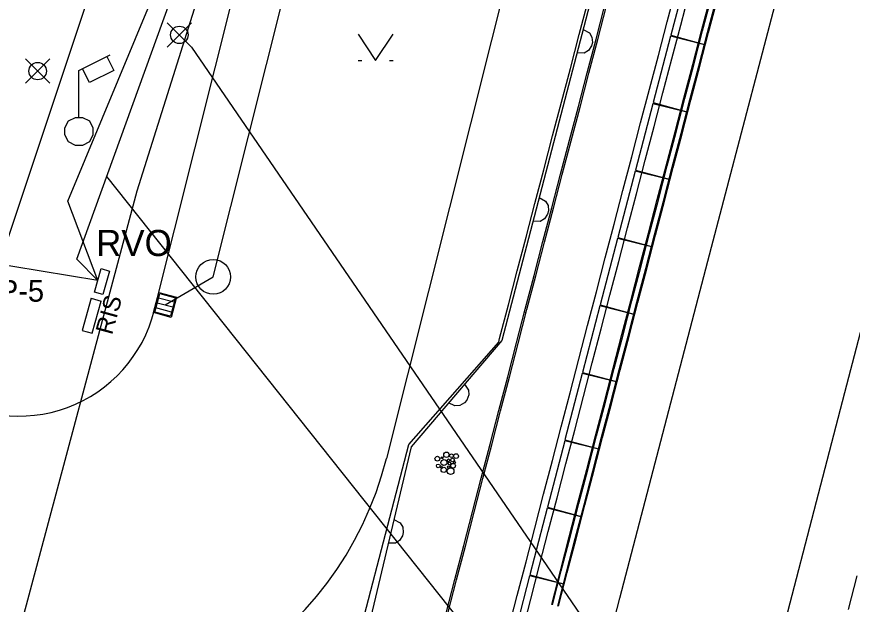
# Model space of a CAD drawing. Extents: x -733601 to -733291, y -1137892 to -1137187.
# Drawn here: x -733460.25 to -733436.26, y -1137631.66 to -1137614.8 of the extents above; entities that cross this region are included whole.
import ezdxf

# ---------------------------------------------------------------- set-up
doc = ezdxf.new("R2010")
doc.units = 0
for name, color, linetype in [('Default', 7, 'Continuous'), ('SIT_PROJ', 7, 'Continuous'), ('SIT_PUV_BUS', 7, 'Continuous'), ('SIT_PUV_ZELEZNICE', 7, 'Continuous')]:
    doc.layers.add(name, color=color, linetype=linetype)

# ---------------------------------------------------------------- blocks, each defined once
blk = doc.blocks.new('DOPRAVA_4$0$SYMB1230')
at = {"layer": 'Default'}
for p, q in [((-0.1, -0.329897), (-0.1, -0.020619)), ((0, -0.020619), (0, -0.329897)), ((0.1, -0.020619), (0.1, -0.329897)), ((-0.1, -0.325773), (-0.1, -0.329897))]:
    blk.add_line(p, q, dxfattribs=at)
for points in [[(-0.2, 0), (0.2, 0), (0.2, -0.35), (-0.2, -0.35)], [(-0.182831, -0.020619), (0.181696, -0.020619), (0.181696, -0.329897), (-0.182831, -0.329897)]]:
    blk.add_lwpolyline(points, close=True, dxfattribs=at)
blk = doc.blocks.new('POINT_DISPLAY')
at = {"layer": 'Default'}
for p, q in [((-0.7, -0.7), (0.7, 0.7)), ((-0.7, 0.7), (0.7, -0.7))]:
    blk.add_line(p, q, dxfattribs=at)
blk.add_circle((0, 0), 0.5, dxfattribs=at)
blk = doc.blocks.new('vytyc_bod_MP')
at = {"layer": 'Default'}
blk.add_blockref('POINT_DISPLAY', (0, 0), dxfattribs=at)

msp = doc.modelspace()

# ---------------------------------------------------------------- linework, layer by layer
at = {"layer": 'SIT_PROJ'}
for points in [[(-733457.917, -1137622.364), (-733458.777, -1137620.095), (-733456.339, -1137614.218), (-733457.273, -1137613.333), (-733455.913, -1137612.939), (-733454.69, -1137608.9), (-733452.562, -1137600.661), (-733449.967, -1137590.732), (-733451.007, -1137589.721), (-733449.679, -1137589.475), (-733444.067, -1137566.075), (-733444.902, -1137565.405), (-733443.754, -1137565.269), (-733437.875, -1137541.673), (-733438.793, -1137541.042), (-733437.71, -1137541.027), (-733436.525, -1137536.63), (-733452.133, -1137532.662), (-733452.807, -1137531.541)], [(-733456.299, -1137623.235), (-733433.573, -1137532.72)], [(-733429.102, -1137545.713), (-733449.631, -1137627.477)], [(-733457.917, -1137622.364), (-733458.523, -1137621.757), (-733455.851, -1137614.377), (-733455.422, -1137613.019), (-733451.725, -1137599.481), (-733449.522, -1137590.912), (-733449.164, -1137589.482), (-733443.392, -1137565.741), (-733438.875, -1137547.904)], [(-733457.917, -1137622.364), (-733464.433, -1137621.3), (-733463.63, -1137616.478), (-733471.299, -1137614.635), (-733471.621, -1137613.836), (-733472.5, -1137612.391), (-733468.724, -1137597.945), (-733462.8, -1137574.579)], [(-733454.604, -1137622.264), (-733444.427, -1137581.731)], [(-733455.227, -1137615.669), (-733439.093, -1137639.217), (-733439.093, -1137639.217)], [(-733457.665, -1137619.387), (-733442.89, -1137637.96), (-733442.89, -1137637.96)], [(-733455.98, -1137623.071), (-733454.604, -1137622.264)]]:
    msp.add_lwpolyline(points, dxfattribs=at)
msp.add_lwpolyline([(-733457.584, -1137622.097), (-733457.771, -1137622.772), (-733458.011, -1137622.701), (-733457.824, -1137622.027)], close=True, dxfattribs=at)
msp.add_lwpolyline([(-733457.584, -1137622.097), (-733457.771, -1137622.772), (-733458.011, -1137622.701), (-733457.824, -1137622.027)], close=True, dxfattribs=at)
msp.add_circle((-733454.604, -1137622.265), 0.5, dxfattribs=at)
for centre, radius, start in [((-733460.178, -1137622.261), 4, 234.8056), ((-733459.33, -1137625.042), 10, 255.9059)]:
    msp.add_arc(centre, radius, start, 345.9059, dxfattribs=at)
at = {"layer": 'SIT_PUV_BUS'}
for p, q in [((-733440.9, -1137603.4), (-733446.32, -1137624.09)), ((-733457.34, -1137611.69), (-733463.99, -1137631.53)), ((-733454.61, -1137612.85), (-733456.8, -1137619.8)), ((-733443.981, -1137615.161), (-733443.8, -1137615.261)), ((-733450.44, -1137615.3), (-733449.94, -1137616.05)), ((-733449.94, -1137616.05), (-733449.44, -1137615.3)), ((-733443.8, -1137615.261), (-733443.729, -1137615.383)), ((-733443.729, -1137615.383), (-733443.719, -1137615.54)), ((-733443.744, -1137615.637), (-733443.831, -1137615.77)), ((-733443.719, -1137615.54), (-733443.744, -1137615.637)), ((-733458.46, -1137616.34), (-733457.56, -1137615.89)), ((-733443.953, -1137615.841), (-733444.159, -1137615.839)), ((-733443.831, -1137615.77), (-733443.953, -1137615.841)), ((-733457.66, -1137615.94), (-733457.46, -1137616.34)), ((-733450.44, -1137616.05), (-733450.34, -1137616.05)), ((-733449.54, -1137616.05), (-733449.44, -1137616.05)), ((-733458.46, -1137617.69), (-733458.46, -1137616.34)), ((-733458.16, -1137616.69), (-733458.36, -1137616.29)), ((-733457.46, -1137616.34), (-733458.16, -1137616.69)), ((-733458.86, -1137617.99), (-733458.76, -1137617.79)), ((-733458.76, -1137617.79), (-733458.56, -1137617.69)), ((-733458.56, -1137617.69), (-733458.36, -1137617.69)), ((-733458.36, -1137617.69), (-733458.16, -1137617.79)), ((-733458.16, -1137617.79), (-733458.06, -1137617.99)), ((-733458.86, -1137618.19), (-733458.86, -1137617.99)), ((-733458.06, -1137617.99), (-733458.06, -1137618.19)), ((-733458.76, -1137618.39), (-733458.86, -1137618.19)), ((-733458.06, -1137618.19), (-733458.16, -1137618.39)), ((-733458.56, -1137618.49), (-733458.76, -1137618.39)), ((-733458.36, -1137618.49), (-733458.56, -1137618.49)), ((-733458.16, -1137618.39), (-733458.36, -1137618.49)), ((-733456.8, -1137619.8), (-733461.75, -1137638.34)), ((-733445.241, -1137619.991), (-733445.06, -1137620.091)), ((-733445.06, -1137620.091), (-733444.989, -1137620.213)), ((-733444.989, -1137620.213), (-733444.979, -1137620.37)), ((-733445.004, -1137620.467), (-733445.091, -1137620.6)), ((-733444.979, -1137620.37), (-733445.004, -1137620.467)), ((-733445.213, -1137620.671), (-733445.419, -1137620.669)), ((-733445.091, -1137620.6), (-733445.213, -1137620.671)), ((-733458.11, -1137622.88), (-733458.37, -1137623.8)), ((-733458.11, -1137622.88), (-733457.82, -1137622.96)), ((-733458.08, -1137623.88), (-733457.82, -1137622.96)), ((-733458.37, -1137623.8), (-733458.08, -1137623.88)), ((-733446.32, -1137624.09), (-733448.92, -1137627.14)), ((-733447.393, -1137625.344), (-733447.273, -1137625.512)), ((-733447.273, -1137625.512), (-733447.262, -1137625.653)), ((-733447.262, -1137625.653), (-733447.321, -1137625.799)), ((-733447.663, -1137625.968), (-733447.847, -1137625.876)), ((-733447.522, -1137625.957), (-733447.663, -1137625.968)), ((-733447.386, -1137625.875), (-733447.522, -1137625.957)), ((-733447.321, -1137625.799), (-733447.386, -1137625.875)), ((-733448.92, -1137627.14), (-733450.78, -1137634.97)), ((-733449.419, -1137629.229), (-733449.236, -1137629.324)), ((-733449.236, -1137629.324), (-733449.162, -1137629.444)), ((-733449.162, -1137629.444), (-733449.148, -1137629.602)), ((-733449.171, -1137629.699), (-733449.254, -1137629.834)), ((-733449.148, -1137629.602), (-733449.171, -1137629.699)), ((-733449.374, -1137629.908), (-733449.581, -1137629.911)), ((-733449.254, -1137629.834), (-733449.374, -1137629.908))]:
    msp.add_line(p, q, dxfattribs=at)
at = {"layer": 'SIT_PUV_ZELEZNICE'}
for p, q in [((-733440.962, -1137613.424), (-733441.464, -1137615.329)), ((-733441.471, -1137615.359), (-733441.972, -1137617.264)), ((-733440.502, -1137615.603), (-733441.471, -1137615.359)), ((-733441.464, -1137615.329), (-733440.499, -1137615.594)), ((-733441.98, -1137617.294), (-733442.48, -1137619.199)), ((-733441.01, -1137617.538), (-733441.98, -1137617.294)), ((-733441.972, -1137617.264), (-733441.008, -1137617.528)), ((-733442.488, -1137619.228), (-733442.987, -1137621.134)), ((-733441.518, -1137619.472), (-733442.488, -1137619.228)), ((-733442.48, -1137619.199), (-733441.516, -1137619.463)), ((-733442.995, -1137621.163), (-733443.494, -1137623.069)), ((-733442.025, -1137621.407), (-733442.995, -1137621.163)), ((-733442.987, -1137621.134), (-733442.023, -1137621.397)), ((-733443.501, -1137623.099), (-733443.999, -1137625.005)), ((-733442.531, -1137623.342), (-733443.501, -1137623.099)), ((-733443.494, -1137623.069), (-733442.529, -1137623.332)), ((-733445.664, -1137623.266), (-733445.615, -1137623.278)), ((-733443.999, -1137625.005), (-733443.034, -1137625.267)), ((-733444.007, -1137625.034), (-733444.504, -1137626.94)), ((-733443.037, -1137625.277), (-733444.007, -1137625.034)), ((-733444.504, -1137626.94), (-733443.539, -1137627.202)), ((-733444.512, -1137626.97), (-733445.008, -1137628.876)), ((-733443.541, -1137627.212), (-733444.512, -1137626.97)), ((-733445.016, -1137628.906), (-733445.511, -1137630.812)), ((-733444.045, -1137629.148), (-733445.016, -1137628.906)), ((-733445.008, -1137628.876), (-733444.043, -1137629.138)), ((-733445.519, -1137630.842), (-733446.014, -1137632.749)), ((-733444.548, -1137631.083), (-733445.519, -1137630.842)), ((-733445.511, -1137630.812), (-733444.546, -1137631.074))]:
    msp.add_line(p, q, dxfattribs=at)
for points in [[(-733469.582, -1137755.14), (-733468.663, -1137751.534), (-733466.195, -1137741.843), (-733463.726, -1137732.153), (-733461.257, -1137722.462), (-733458.789, -1137712.772), (-733456.32, -1137703.081), (-733453.852, -1137693.391), (-733451.383, -1137683.701), (-733451.044, -1137682.371), (-733448.914, -1137674.01), (-733446.443, -1137664.32), (-733443.966, -1137654.632), (-733441.48, -1137644.946), (-733438.982, -1137635.263), (-733436.47, -1137625.584), (-733433.94, -1137615.909), (-733431.39, -1137606.239), (-733431.038, -1137604.913), (-733428.815, -1137596.577), (-733426.217, -1137586.92), (-733424.808, -1137581.736)], [(-733473.591, -1137751.638), (-733472.603, -1137747.76), (-733470.135, -1137738.069), (-733467.666, -1137728.379), (-733465.198, -1137718.688), (-733462.729, -1137708.998), (-733460.26, -1137699.307), (-733457.792, -1137689.617), (-733455.323, -1137679.926), (-733452.855, -1137670.236), (-733450.386, -1137660.545), (-733448.734, -1137654.061), (-733447.917, -1137650.855), (-733445.432, -1137641.168), (-733442.928, -1137631.487), (-733440.405, -1137621.811), (-733437.862, -1137612.139), (-733437.8, -1137611.906), (-733435.314, -1137602.469), (-733432.775, -1137592.797), (-733432.613, -1137592.177)], [(-733446.408, -1137624.136), (-733446.381, -1137624.034), (-733446.128, -1137623.065), (-733445.875, -1137622.095), (-733445.621, -1137621.126), (-733445.367, -1137620.157), (-733445.113, -1137619.188), (-733444.859, -1137618.218), (-733444.605, -1137617.249), (-733444.35, -1137616.28), (-733444.096, -1137615.311), (-733443.841, -1137614.342), (-733443.586, -1137613.373), (-733443.33, -1137612.404), (-733443.075, -1137611.435), (-733442.819, -1137610.466), (-733442.563, -1137609.498), (-733442.308, -1137608.53), (-733442.053, -1137607.562), (-733441.797, -1137606.594), (-733441.542, -1137605.626), (-733441.287, -1137604.658), (-733441.032, -1137603.69), (-733440.951, -1137603.382)], [(-733446.125, -1137632.38), (-733445.873, -1137631.411), (-733445.622, -1137630.442), (-733445.37, -1137629.473), (-733445.118, -1137628.504), (-733444.866, -1137627.535), (-733444.613, -1137626.566), (-733444.36, -1137625.597), (-733444.108, -1137624.628), (-733443.854, -1137623.659), (-733443.601, -1137622.69), (-733443.348, -1137621.721), (-733443.094, -1137620.752), (-733442.84, -1137619.784), (-733442.586, -1137618.815), (-733442.332, -1137617.846), (-733442.078, -1137616.877), (-733441.823, -1137615.909), (-733441.568, -1137614.94), (-733441.313, -1137613.972)], [(-733445.738, -1137632.481), (-733445.486, -1137631.512), (-733445.235, -1137630.542), (-733444.983, -1137629.573), (-733444.731, -1137628.604), (-733444.478, -1137627.635), (-733444.226, -1137626.667), (-733443.973, -1137625.698), (-733443.721, -1137624.729), (-733443.467, -1137623.76), (-733443.214, -1137622.791), (-733442.961, -1137621.822), (-733442.707, -1137620.854), (-733442.453, -1137619.885), (-733442.199, -1137618.916), (-733441.945, -1137617.948), (-733441.691, -1137616.979), (-733441.436, -1137616.01), (-733441.181, -1137615.042), (-733440.926, -1137614.073)], [(-733444.886, -1137631.667), (-733444.634, -1137630.698), (-733444.383, -1137629.729), (-733444.131, -1137628.761), (-733443.878, -1137627.792), (-733443.626, -1137626.823), (-733443.373, -1137625.854), (-733443.121, -1137624.885), (-733442.868, -1137623.917), (-733442.614, -1137622.948), (-733442.361, -1137621.979), (-733442.107, -1137621.011), (-733441.854, -1137620.042), (-733441.6, -1137619.074), (-733441.345, -1137618.105), (-733441.091, -1137617.137), (-733440.836, -1137616.168), (-733440.582, -1137615.2), (-733440.327, -1137614.231)], [(-733447.916, -1137631.916), (-733447.664, -1137630.946), (-733447.412, -1137629.977), (-733447.16, -1137629.007), (-733446.908, -1137628.038), (-733446.656, -1137627.068), (-733446.403, -1137626.099), (-733446.15, -1137625.13), (-733445.898, -1137624.16), (-733445.644, -1137623.191), (-733445.391, -1137622.222), (-733445.138, -1137621.253), (-733444.884, -1137620.284), (-733444.63, -1137619.314), (-733444.376, -1137618.345), (-733444.121, -1137617.376), (-733443.867, -1137616.407), (-733443.612, -1137615.438), (-733443.357, -1137614.469)], [(-733444.863, -1137631.673), (-733444.611, -1137630.704), (-733444.358, -1137629.736), (-733444.105, -1137628.767), (-733443.852, -1137627.798), (-733443.599, -1137626.83), (-733443.345, -1137625.861), (-733443.092, -1137624.893), (-733442.838, -1137623.924), (-733442.584, -1137622.956), (-733442.331, -1137621.987), (-733442.077, -1137621.019), (-733441.824, -1137620.05), (-733441.57, -1137619.081), (-733441.316, -1137618.113), (-733441.063, -1137617.144), (-733440.809, -1137616.176), (-733440.555, -1137615.207), (-733440.302, -1137614.238)], [(-733444.712, -1137631.712), (-733444.46, -1137630.744), (-733444.208, -1137629.775), (-733443.956, -1137628.806), (-733443.704, -1137627.837), (-733443.452, -1137626.868), (-733443.199, -1137625.9), (-733442.946, -1137624.931), (-733442.693, -1137623.962), (-733442.44, -1137622.994), (-733442.187, -1137622.025), (-733441.933, -1137621.056), (-733441.68, -1137620.088), (-733441.426, -1137619.119), (-733441.171, -1137618.151), (-733440.917, -1137617.182), (-733440.662, -1137616.214), (-733440.408, -1137615.246), (-733440.153, -1137614.277)], [(-733444.689, -1137631.718), (-733444.437, -1137630.75), (-733444.184, -1137629.781), (-733443.931, -1137628.812), (-733443.678, -1137627.844), (-733443.425, -1137626.875), (-733443.171, -1137625.907), (-733442.918, -1137624.938), (-733442.664, -1137623.97), (-733442.41, -1137623.001), (-733442.157, -1137622.033), (-733441.903, -1137621.064), (-733441.649, -1137620.096), (-733441.396, -1137619.127), (-733441.142, -1137618.158), (-733440.889, -1137617.19), (-733440.635, -1137616.221), (-733440.381, -1137615.252), (-733440.128, -1137614.284)], [(-733447.867, -1137631.928), (-733447.616, -1137630.959), (-733447.364, -1137629.989), (-733447.112, -1137629.02), (-733446.86, -1137628.05), (-733446.607, -1137627.081), (-733446.355, -1137626.112), (-733446.102, -1137625.142), (-733445.849, -1137624.173), (-733445.596, -1137623.204), (-733445.343, -1137622.235), (-733445.089, -1137621.265), (-733444.835, -1137620.296), (-733444.581, -1137619.327), (-733444.327, -1137618.358), (-733444.073, -1137617.389), (-733443.818, -1137616.42), (-733443.564, -1137615.451), (-733443.309, -1137614.482)], [(-733450.929, -1137634.537), (-733448.984, -1137627.078), (-733446.408, -1137624.136)], [(-733436.363, -1137631.81), (-733436.112, -1137630.842)]]:
    msp.add_lwpolyline(points, dxfattribs=at)
for centre, radius in [((-733448.168, -1137627.483), 0.0687), ((-733448.034, -1137627.456), 0.0259), ((-733447.909, -1137627.37), 0.0777), ((-733447.766, -1137627.399), 0.0522), ((-733447.63, -1137627.408), 0.0686), ((-733448.142, -1137627.691), 0.0528), ((-733447.981, -1137627.593), 0.0864), ((-733447.852, -1137627.53), 0.0388), ((-733447.818, -1137627.621), 0.0404), ((-733447.734, -1137627.521), 0.0528), ((-733447.717, -1137627.684), 0.0672), ((-733447.68, -1137627.593), 0.0278), ((-733448.063, -1137627.718), 0.027), ((-733447.986, -1137627.804), 0.0752), ((-733447.787, -1137627.839), 0.0954), ((-733447.845, -1137627.723), 0.0323)]:
    msp.add_circle(centre, radius, dxfattribs=at)

# ---------------------------------------------------------------- block references
at = {"layer": 'SIT_PROJ', "xscale": 0.5, "yscale": 0.5}
for p in [(-733455.577, -1137615.319), (-733459.645, -1137616.359)]:
    msp.add_blockref('vytyc_bod_MP', p, dxfattribs=at)
at = {"layer": 'SIT_PROJ', "xscale": 1.4999999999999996, "yscale": 1.4999999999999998, "rotation": 75.020036}
msp.add_blockref('DOPRAVA_4$0$SYMB1230', (-733456.24, -1137623.001), dxfattribs=at)

# ---------------------------------------------------------------- texts
at = {"layer": 'SIT_PROJ'}
msp.add_text('RVO', height=0.75, dxfattribs=at).set_placement((-733457.967, -1137621.667))
msp.add_text('ZIP-5', height=0.625, rotation=360, dxfattribs=at).set_placement((-733461.503, -1137622.977))
at = {"layer": 'SIT_PUV_BUS'}
msp.add_text('RIS', height=0.5, rotation=74.7, dxfattribs=at).set_placement((-733457.51, -1137623.95))

doc.saveas('drawing.dxf')
